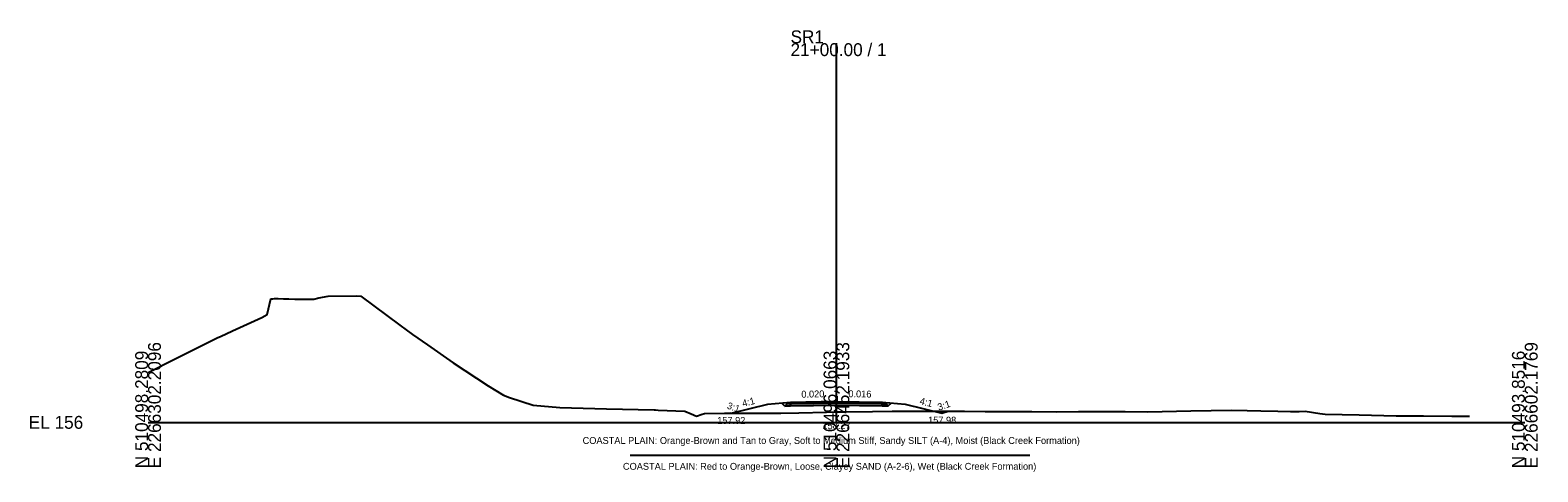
# Model space of a CAD drawing. Extents: x -1079 to 303, y -11 to 4017.
# Drawn here: x -25.7 to 302.8, y -10.8 to 85.4 of the extents above; entities that cross this region are included whole.
import ezdxf

# ---------------------------------------------------------------- set-up
doc = ezdxf.new("R2010")
doc.units = 0
for name, color, linetype in [('Default', 7, 'Continuous'), ('Exist Cross Section Cell', 7, 'Continuous'), ('Exist XS Center Line Elevation Label', 7, 'Continuous'), ('Exist XS Ground Line', 7, 'Continuous'), ('Prop CMT Pvmt Course 1', 7, 'Continuous'), ('Prop CMT Pvmt Course 2', 7, 'Continuous'), ('Prop CMT Pvmt Course 3', 7, 'Continuous'), ('Prop CMT Pvmt Surface', 7, 'Continuous'), ('Prop CMT Pvmt Surface Shoulder', 7, 'Continuous'), ('Prop CMT Shld Paved Course 1', 7, 'Continuous'), ('Prop CMT Shld Paved Course 2', 7, 'Continuous'), ('Prop CMT Shld Paved Course 3', 7, 'Continuous'), ('Prop CMT Slope Grass', 7, 'Continuous'), ('Prop CMT Subgrade Earthwork', 7, 'Continuous'), ('Prop Road Sect_ Material - Contact (General - Minor)', 7, 'Continuous'), ('Prop Road Sect_ Material - Tx (Composite Desc)', 7, 'Continuous'), ('Prop XS Ditch Standard Text', 7, 'Continuous'), ('Prop XS SE Text', 7, 'Continuous'), ('Prop XS Side Slope Text', 7, 'Continuous')]:
    doc.layers.add(name, color=color, linetype=linetype)

msp = doc.modelspace()

# ---------------------------------------------------------------- linework, layer by layer
at = {"layer": 'Exist Cross Section Cell'}
for p, q in [((150, 0), (150, 82.58)), ((0, 0), (150, 0)), ((150, 0), (300, 0))]:
    msp.add_line(p, q, dxfattribs=at)
at = {"layer": 'Exist XS Ground Line'}
msp.add_lwpolyline([(0, 10.88), (5.94, 13.82), (15.17, 18.45), (15.8, 18.73), (18.39, 19.93), (24.76, 22.86), (25.96, 23.46), (26.72, 26.89), (27.17, 26.94), (27.56, 26.96), (28.32, 26.95), (29.51, 26.93), (30.69, 26.88), (32.01, 26.84), (33.16, 26.83), (34.5, 26.83), (35.02, 26.84), (36.12, 26.85), (37.24, 27.11), (39.25, 27.48), (45.46, 27.53), (46.39, 27.52), (54.88, 21.19), (57.61, 19.11), (60.92, 16.86), (66.5, 12.93), (74.14, 7.99), (77.43, 5.9), (78.78, 5.4), (83.89, 3.72), (89.74, 3.21), (99.9, 2.96), (110.26, 2.72), (110.58, 2.71), (111.17, 2.68), (116.95, 2.4), (118.38, 1.86), (119.5, 1.38), (120.71, 1.81), (121.24, 1.96), (125.58, 1.97), (137.86, 2.03), (141.82, 2.07), (147.87, 2.24), (150, 2.27), (151.98, 2.29), (157.87, 2.39), (162.13, 2.42), (167.87, 2.46), (172.28, 2.45), (177.87, 2.41), (182.43, 2.37), (187.88, 2.39), (192.59, 2.33), (197.88, 2.31), (202.74, 2.37), (207.88, 2.33), (212.89, 2.35), (217.88, 2.32), (227.25, 2.48), (236.05, 2.64), (239.53, 2.57), (242.45, 2.52), (246.19, 2.42), (248.94, 2.36), (250.8, 2.38), (252.15, 2.4), (255.34, 1.94), (256.49, 1.8), (263.89, 1.61), (271.95, 1.44), (277.94, 1.43), (284.11, 1.35), (287.95, 1.35)], dxfattribs=at)
at = {"layer": 'Prop CMT Pvmt Course 1'}
for points in [[(150, 4.52), (140, 4.32)], [(140, 4.32), (140, 4.07)], [(140, 4.07), (150, 4.27)], [(150, 4.27), (150, 4.52)], [(150, 4.52), (160, 4.36)], [(150, 4.27), (150, 4.52)], [(160, 4.11), (150, 4.27)], [(160, 4.36), (160, 4.11)]]:
    msp.add_lwpolyline(points, dxfattribs=at)
msp.add_lwpolyline([(150, 4.27), (150, 4.39), (150, 4.39), (150, 4.27)], close=True, dxfattribs=at)
msp.add_lwpolyline([(150, 4.27), (150, 4.39), (150, 4.39), (150, 4.27)], close=True, dxfattribs=at)
at = {"layer": 'Prop CMT Pvmt Course 2'}
for points in [[(140, 4.07), (150, 4.27)], [(150, 4.27), (140, 4.07)], [(140, 4.07), (140, 4.07)], [(150, 4.27), (150, 4.27)], [(160, 4.11), (150, 4.27)], [(150, 4.27), (150, 4.27)], [(150, 4.27), (160, 4.11)], [(160, 4.11), (160, 4.11)]]:
    msp.add_lwpolyline(points, dxfattribs=at)
at = {"layer": 'Prop CMT Pvmt Course 3'}
for points in [[(150, 4.27), (140, 4.07)], [(140, 4.07), (140, 3.57)], [(140, 3.57), (150, 3.77)], [(150, 3.77), (150, 4.27)], [(150, 4.27), (160, 4.11)], [(150, 3.77), (150, 4.27)], [(160, 3.61), (150, 3.77)], [(160, 4.11), (160, 3.61)]]:
    msp.add_lwpolyline(points, dxfattribs=at)
at = {"layer": 'Prop CMT Pvmt Surface'}
for q in [(140, 4.32), (160, 4.36)]:
    msp.add_line((150, 4.52), q, dxfattribs=at)
at = {"layer": 'Prop CMT Pvmt Surface Shoulder'}
for p, q in [((140, 4.32), (140, 4.32)), ((160, 4.36), (160, 4.36))]:
    msp.add_line(p, q, dxfattribs=at)
at = {"layer": 'Prop CMT Shld Paved Course 1'}
for points in [[(140, 4.32), (140, 4.32), (139.74, 4.06)], [(139.74, 4.06), (140, 4.07)], [(140, 4.07), (140, 4.32)], [(160, 4.36), (160, 4.36), (160.26, 4.1)], [(160, 4.11), (160, 4.36)], [(160.26, 4.1), (160, 4.11)]]:
    msp.add_lwpolyline(points, dxfattribs=at)
at = {"layer": 'Prop CMT Shld Paved Course 2'}
for points in [[(140, 4.07), (139.74, 4.06)], [(139.74, 4.06), (140, 4.07)], [(139.74, 4.06), (139.74, 4.06)], [(140, 4.07), (140, 4.07)], [(160, 4.11), (160.26, 4.1)], [(160.26, 4.1), (160, 4.11)], [(160, 4.11), (160, 4.11)], [(160.26, 4.1), (160.26, 4.1)]]:
    msp.add_lwpolyline(points, dxfattribs=at)
at = {"layer": 'Prop CMT Shld Paved Course 3'}
for points in [[(140, 4.07), (139.74, 4.06), (139.24, 4.05), (138.73, 3.54)], [(138.73, 3.54), (140, 3.57)], [(140, 3.57), (140, 4.07)], [(160, 4.11), (160.26, 4.1), (160.76, 4.1), (161.26, 3.59)], [(160, 3.61), (160, 4.11)], [(161.26, 3.59), (160, 3.61)]]:
    msp.add_lwpolyline(points, dxfattribs=at)
at = {"layer": 'Prop CMT Slope Grass'}
for p, q in [((135, 3.92), (127, 1.92)), ((140, 4.32), (135, 3.92)), ((160, 4.36), (165, 3.98)), ((165, 3.98), (173, 1.98)), ((127, 1.92), (126.84, 1.97)), ((173, 1.98), (174.37, 2.43))]:
    msp.add_line(p, q, dxfattribs=at)
at = {"layer": 'Prop CMT Subgrade Earthwork'}
for points in [[(138.73, 3.54), (138.11, 4.17)], [(140, 3.57), (138.73, 3.54)], [(150, 3.77), (140, 3.57)], [(150, 3.77), (160, 3.61)], [(160, 3.61), (161.26, 3.59)], [(161.26, 3.59), (161.89, 4.21)]]:
    msp.add_lwpolyline(points, dxfattribs=at)
at = {"layer": 'Prop Road Sect_ Material - Contact (General - Minor)'}
msp.add_line((192.13, -7.2), (105.04, -7.2), dxfattribs=at)

# ---------------------------------------------------------------- texts
at = {"layer": 'Default'}
msp.add_text('-', height=0.0001, dxfattribs=at).set_placement((0, 0))
at = {"layer": 'Exist Cross Section Cell'}
for s, p in [('SR1', (140, 82.58)), ('21+00.00 / 1', (140, 79.78)), ('EL 156', (-26, -1.4))]:
    msp.add_text(s, height=2.8, dxfattribs=at).set_placement(p)
for s, p in [('E 2266302.2096', (2.8, -10)), ('E 2266452.1933', (152.8, -10)), ('E 2266602.1769', (302.8, -10)), ('N 510498.2809', (0, -10)), ('N 510496.0663', (150, -10)), ('N 510493.8516', (300, -10))]:
    msp.add_text(s, height=2.8, rotation=90, dxfattribs=at).set_placement(p)
at = {"layer": 'Exist XS Center Line Elevation Label'}
msp.add_text('158.27', height=1.5, dxfattribs=at).set_placement((146.95, -1.48))
at = {"layer": 'Prop Road Sect_ Material - Tx (Composite Desc)'}
for s, p in [('COASTAL PLAIN: Orange-Brown and Tan to Gray, Soft to Medium Stiff, Sandy SILT (A-4), Moist (Black Creek Formation)', (94.69, -4.7)), ('COASTAL PLAIN: Red to Orange-Brown, Loose, Clayey SAND (A-2-6), Wet (Black Creek Formation)', (103.48, -10.33))]:
    msp.add_text(s, height=1.5, dxfattribs=at).set_placement(p)
at = {"layer": 'Prop XS Ditch Standard Text'}
for s, p in [('157.92', (124.02, -0.33)), ('157.98', (169.97, -0.27))]:
    msp.add_text(s, height=1.5, dxfattribs=at).set_placement(p)
at = {"layer": 'Prop XS SE Text'}
for s, rotation, p in [('0.020', 1.1458, (142.36, 5.37)), ('0.016', 359.0724, (152.59, 5.48))]:
    msp.add_text(s, height=1.5, rotation=rotation, dxfattribs=at).set_placement(p)
at = {"layer": 'Prop XS Side Slope Text'}
for s, rotation, p in [('3:1', 341.5668, (126.03, 3.03)), ('4:1', 14.0362, (129.66, 3.36)), ('4:1', 345.9638, (168.03, 3.99)), ('3:1', 18.4332, (172.32, 2.54))]:
    msp.add_text(s, height=1.5, rotation=rotation, dxfattribs=at).set_placement(p)

doc.saveas('drawing.dxf')
